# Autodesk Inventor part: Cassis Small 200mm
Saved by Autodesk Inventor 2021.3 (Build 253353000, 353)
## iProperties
Created: 2023-09
Part Number: Cassis Small 200mm
Material: Generic
Document SubType Name: Modeling
Designer: AdminForWorker
Density: 1 g/cm^3
Appearance: Default
Title: Cassis Small 200mm v1
Author: AdminForWorker
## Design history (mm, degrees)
feature "Body1"
feature "Body2"
feature "Body3"
feature "Body4"
feature "Body5"
feature "Body6"
body "Solid1"
body "Solid2"
body "Solid3"
body "Solid4"
body "Solid5"
body "Solid6"
